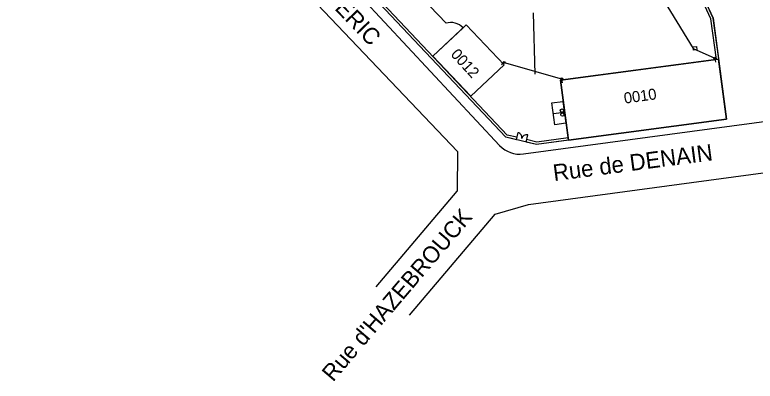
# Model space of a CAD drawing. Extents: x 703432 to 707394, y 7057985 to 7059523.
# Drawn here: x 704446.8 to 704581.3, y 7058908.7 to 7058975.3 of the extents above; entities that cross this region are included whole.
import ezdxf

# ---------------------------------------------------------------- set-up
doc = ezdxf.new("R2010")
doc.units = 0
for name, color, linetype in [('DH_HACHURE-MOTIF', 7, 'Continuous'), ('DH_TEXTE', 7, 'Continuous'), ('GO_MUR_EXTERIEUR', 7, 'Continuous'), ('IMM_LIMITE PHYSIQUE', 7, 'Continuous'), ('R_PLU_CANALISATION_CL_A', 7, 'Continuous'), ('SID_NUMERO_BATI', 7, 'Continuous'), ('SID_POLYLIGNES_BATI', 7, 'Continuous'), ('SID_POLYLIGNES_IMMEUBLE', 7, 'Continuous'), ('SO_EP_EQUIP', 7, 'Continuous'), ('VOIRIE_BORDURE', 7, 'Continuous'), ('VOIRIE_ROUTE', 7, 'Continuous')]:
    doc.layers.add(name, color=color, linetype=linetype)

msp = doc.modelspace()

# ---------------------------------------------------------------- linework, layer by layer
at = {"layer": 'DH_HACHURE-MOTIF'}
for points in [[(704528.21, 7058972.98), (704522.75, 7058967.83), (704529.61, 7058960.55), (704535.66, 7058966.26), (704528.79, 7058973.53), (704528.21, 7058972.98)], [(704547.3, 7058952.98), (704547.36, 7058952.53), (704576.1, 7058956.39), (704574.64, 7058967.29), (704574.19, 7058967.23), (704545.9, 7058963.43), (704547.3, 7058952.98)]]:
    msp.add_lwpolyline(points, dxfattribs=at)
at = {"layer": 'GO_MUR_EXTERIEUR'}
for p, q in [((704522.75, 7058967.83), (704528.79, 7058973.53)), ((704528.79, 7058973.53), (704535.66, 7058966.26)), ((704529.61, 7058960.55), (704522.75, 7058967.83)), ((704545.9, 7058963.43), (704574.64, 7058967.29)), ((704574.64, 7058967.29), (704576.1, 7058956.39)), ((704535.66, 7058966.26), (704529.61, 7058960.55)), ((704547.36, 7058952.53), (704545.9, 7058963.43)), ((704576.1, 7058956.39), (704547.36, 7058952.53))]:
    msp.add_line(p, q, dxfattribs=at)
at = {"layer": 'IMM_LIMITE PHYSIQUE'}
for p, q in [((704472.28, 7059020.59), (704535.98, 7058953.07)), ((704472.61, 7059020.9), (704536.21, 7058953.48)), ((704537.91, 7058952.62), (704535.98, 7058953.07)), ((704538.01, 7058953.06), (704536.21, 7058953.48)), ((704537.91, 7058952.62), (704538.21, 7058953.91)), ((704539.66, 7058952.21), (704539.96, 7058953.5)), ((704547.3, 7058952.98), (704541.61, 7058952.21)), ((704541.59, 7058951.76), (704539.66, 7058952.21)), ((704541.61, 7058952.21), (704539.76, 7058952.65)), ((704547.36, 7058952.53), (704541.59, 7058951.76))]:
    msp.add_line(p, q, dxfattribs=at)
for points in [[(704574.25, 7058967.23), (704573.22, 7058974.58), (704565.32, 7058991.86)], [(704574.7, 7058967.3), (704573.66, 7058974.71), (704565.73, 7058992.05)]]:
    msp.add_lwpolyline(points, dxfattribs=at)
for centre, start, end in [((704538.04, 7058953.05), 346.7916, 78.7098), ((704539.74, 7058952.65), 75.2683, 166.7916)]:
    msp.add_arc(centre, 0.874, start, end, dxfattribs=at)
at = {"layer": 'R_PLU_CANALISATION_CL_A'}
for p, q in [((704541.33, 7058964.53), (704541.03, 7058975.68)), ((704535.69, 7058966.65), (704535.23, 7058966.21)), ((704535.69, 7058966.65), (704546.13, 7058963.69)), ((704573.99, 7058967.43), (704574.09, 7058966.7)), ((704546.13, 7058963.69), (704546.2, 7058962.97)), ((704546.61, 7058957.6), (704544.63, 7058957.33))]:
    msp.add_line(p, q, dxfattribs=at)
for points in [[(704561.77, 7058982.71), (704570.05, 7058969.19), (704573.99, 7058967.43)], [(704570.69, 7058968.98), (704570.09, 7058968.89), (704570.01, 7058969.49), (704570.61, 7058969.57), (704570.69, 7058968.98)], [(704546.88, 7058955.61), (704544.89, 7058955.35), (704544.36, 7058959.31), (704546.34, 7058959.58), (704546.88, 7058955.61)]]:
    msp.add_lwpolyline(points, dxfattribs=at)
for centre in [(704546.19, 7058957.91), (704546.28, 7058957.19)]:
    msp.add_circle(centre, 0.3, dxfattribs=at)
at = {"layer": 'SID_POLYLIGNES_BATI'}
for p, q in [((704522.75, 7058967.83), (704528.79, 7058973.53)), ((704528.79, 7058973.53), (704535.66, 7058966.26)), ((704529.61, 7058960.55), (704522.75, 7058967.83)), ((704545.9, 7058963.43), (704574.64, 7058967.29)), ((704574.64, 7058967.29), (704576.1, 7058956.39)), ((704535.66, 7058966.26), (704529.61, 7058960.55)), ((704547.36, 7058952.53), (704545.9, 7058963.43)), ((704576.1, 7058956.39), (704547.36, 7058952.53))]:
    msp.add_line(p, q, dxfattribs=at)
at = {"layer": 'SID_POLYLIGNES_IMMEUBLE'}
for p, q in [((704535.98, 7058953.07), (704446.77, 7059047.64)), ((704565.73, 7058992.05), (704573.66, 7058974.71)), ((704573.66, 7058974.71), (704576.1, 7058956.39))]:
    msp.add_line(p, q, dxfattribs=at)
msp.add_lwpolyline([(704576.1, 7058956.39), (704541.59, 7058951.76), (704535.98, 7058953.07)], dxfattribs=at)
at = {"layer": 'SO_EP_EQUIP'}
for centre in [(704573.99, 7058967.43), (704535.69, 7058966.65), (704546.13, 7058963.69)]:
    msp.add_circle(centre, 0.2, dxfattribs=at)
at = {"layer": 'VOIRIE_BORDURE'}
msp.add_line((704514.85, 7058984.67), (704525.12, 7058973.78), dxfattribs=at)
msp.add_arc((704526.03, 7058970.92), 3, 43.3308, 107.6513, dxfattribs=at)
at = {"layer": 'VOIRIE_ROUTE'}
for p, q in [((704527.18, 7058950.47), (704470.47, 7059010.13)), ((704482.54, 7059007.66), (704534.87, 7058951.59)), ((704527.18, 7058950.47), (704527.15, 7058943.25)), ((704512.42, 7058925.88), (704527.15, 7058943.25))]:
    msp.add_line(p, q, dxfattribs=at)
for points in [[(704539.19, 7058950.05), (704592.38, 7058957.19)], [(704518.49, 7058920.73), (704534.04, 7058939.07), (704540.1, 7058940.88), (704592.62, 7058947.93)]]:
    msp.add_lwpolyline(points, dxfattribs=at)
msp.add_arc((704538.52, 7058955), 5, 223.0213, 277.6524, dxfattribs=at)

# ---------------------------------------------------------------- texts
at = {"layer": 'DH_TEXTE'}
for s, rotation, p in [('Rue LYDERIC', 313.8024, (704493.48, 7058988.15)), ('Rue de DENAIN', 7.4746, (704544.76, 7058945.1)), ("Rue d'HAZEBROUCK", 49.6268, (704504.6, 7058908.49))]:
    msp.add_text(s, height=3, rotation=rotation, dxfattribs=at).set_placement(p)
at = {"layer": 'SID_NUMERO_BATI'}
for s, rotation, p in [('0012', 312.5129, (704525.86, 7058968.04)), ('0010', 8.0003, (704557.59, 7058959.17))]:
    msp.add_text(s, height=2, rotation=rotation, dxfattribs=at).set_placement(p)

doc.saveas('drawing.dxf')
